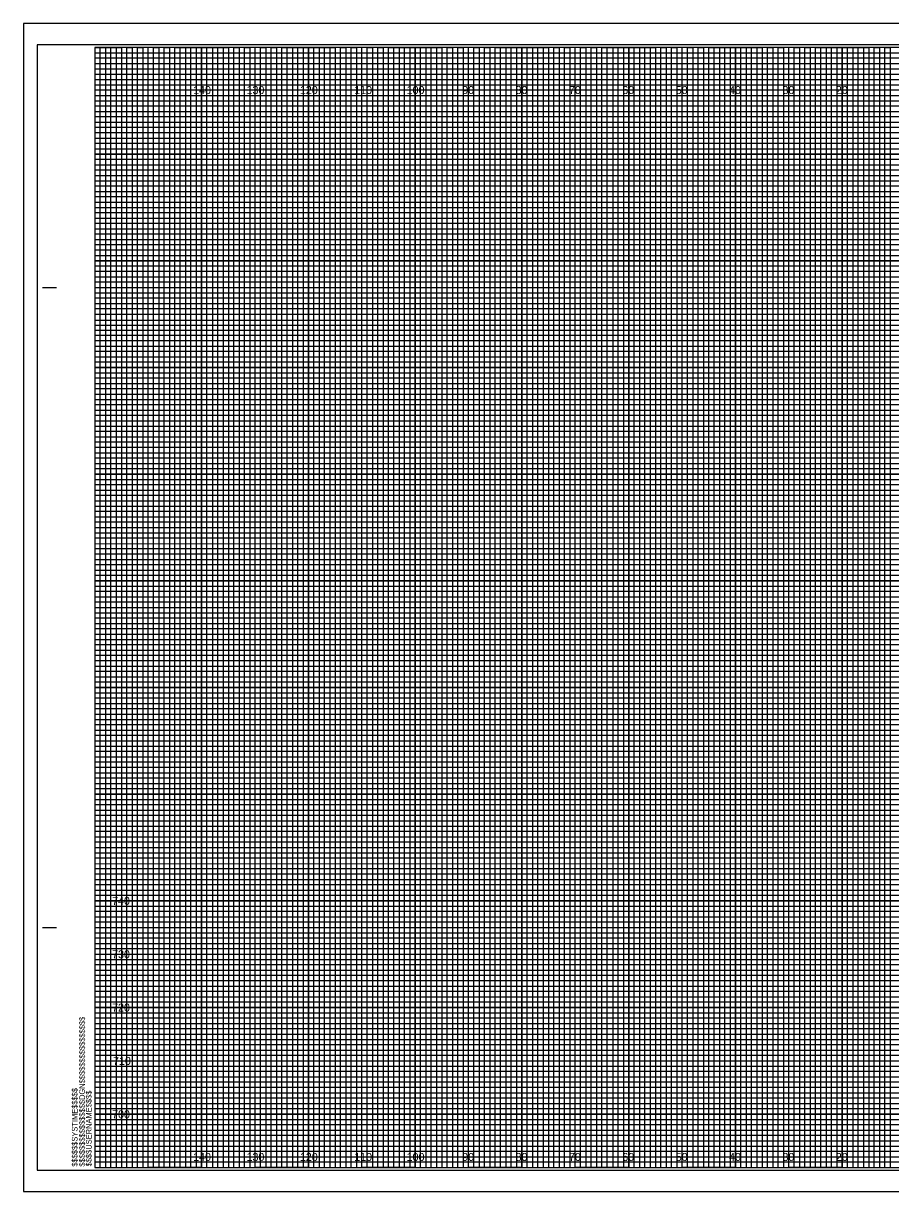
# Model space of a CAD drawing. Extents: x -13 to 323, y -5 to 534.
# Drawn here: x -13.4 to 149.1, y 315.5 to 534.5 of the extents above; entities that cross this region are included whole.
import ezdxf

# ---------------------------------------------------------------- set-up
doc = ezdxf.new("R2010")
doc.units = 0
for name, color, linetype in [('Prop XS Elevation Labels', 7, 'Continuous'), ('Prop XS Offset Labels', 7, 'Continuous'), ('Sheet Cross Section CELL', 7, 'Continuous'), ('Sheet Cross Section Grid Major CELL', 7, 'Continuous'), ('Sheet Cross Section Grid Middle CELL', 7, 'Continuous'), ('Sheet Cross Section Grid Minor 1 CELL', 7, 'Continuous'), ('Sheet Cross Section Grid Minor 2 CELL', 7, 'Continuous'), ('Sheet Cutting Line CELL', 7, 'Continuous'), ('Sheet DOT Grid CELL', 7, 'Continuous'), ('Sheet Plot Border Inside CELL', 7, 'Continuous'), ('Sheet Plot Border Outside CELL', 7, 'Continuous')]:
    doc.layers.add(name, color=color, linetype=linetype)

msp = doc.modelspace()

# ---------------------------------------------------------------- linework, layer by layer
at = {"layer": 'Sheet Cross Section CELL'}
for p, q in [((-9.8, 485), (-7.3, 485)), ((-9.7, 485), (-7.2, 485)), ((-9.8, 365), (-7.3, 365)), ((-9.7, 365), (-7.2, 365))]:
    msp.add_line(p, q, dxfattribs=at)
msp.add_lwpolyline([(320, 530), (0, 530), (0, 320), (320, 320)], close=True, dxfattribs=at)
at = {"layer": 'Sheet Cross Section Grid Major CELL'}
for p, q in [((10, 530), (0, 530)), ((10, 320), (10, 530)), ((30, 530), (20, 530)), ((20, 530), (20, 320)), ((30, 320), (30, 530)), ((50, 530), (40, 530)), ((40, 530), (40, 320)), ((50, 320), (50, 530)), ((70, 530), (60, 530)), ((60, 530), (60, 320)), ((70, 320), (70, 530)), ((90, 530), (80, 530)), ((80, 530), (80, 320)), ((90, 320), (90, 530)), ((110, 530), (100, 530)), ((100, 530), (100, 320)), ((110, 320), (110, 530)), ((130, 530), (120, 530)), ((120, 530), (120, 320)), ((130, 320), (130, 530)), ((150, 530), (140, 530)), ((140, 530), (140, 320)), ((20, 320), (10, 320)), ((40, 320), (30, 320)), ((60, 320), (50, 320)), ((80, 320), (70, 320)), ((100, 320), (90, 320)), ((120, 320), (110, 320)), ((140, 320), (130, 320))]:
    msp.add_line(p, q, dxfattribs=at)
for points in [[(0, 520), (320, 520), (320, 510), (0, 510)], [(0, 500), (320, 500), (320, 490), (0, 490)], [(0, 480), (320, 480), (320, 470), (0, 470)], [(0, 460), (320, 460), (320, 450), (0, 450)], [(0, 440), (320, 440), (320, 430), (0, 430)], [(0, 420), (320, 420), (320, 410), (0, 410)], [(0, 400), (320, 400), (320, 390), (0, 390)], [(0, 380), (320, 380), (320, 370), (0, 370)], [(0, 360), (320, 360), (320, 350), (0, 350)], [(0, 340), (320, 340), (320, 330), (0, 330)]]:
    msp.add_lwpolyline(points, dxfattribs=at)
at = {"layer": 'Sheet Cross Section Grid Middle CELL'}
for points in [[(0, 530), (5, 530), (5, 320), (15, 320), (15, 530), (25, 530), (25, 320), (35, 320), (35, 530), (45, 530), (45, 320), (55, 320), (55, 530), (65, 530), (65, 320), (75, 320), (75, 530), (85, 530), (85, 320), (95, 320), (95, 530), (105, 530), (105, 320), (115, 320), (115, 530), (125, 530), (125, 320), (135, 320), (135, 530), (145, 530), (145, 320), (155, 320)], [(0, 525), (275, 525)], [(0, 505), (320, 505), (320, 515), (0, 515)], [(0, 485), (320, 485), (320, 495), (0, 495)], [(0, 465), (320, 465), (320, 475), (0, 475)], [(0, 445), (320, 445), (320, 455), (0, 455)], [(0, 425), (320, 425), (320, 435), (0, 435)], [(0, 405), (320, 405), (320, 415), (0, 415)], [(0, 385), (320, 385), (320, 395), (0, 395)], [(0, 365), (320, 365), (320, 375), (0, 375)], [(0, 345), (320, 345), (320, 355), (0, 355)], [(0, 325), (320, 325), (320, 335), (0, 335)]]:
    msp.add_lwpolyline(points, dxfattribs=at)
at = {"layer": 'Sheet Cross Section Grid Minor 1 CELL'}
for p, q in [((0, 529), (260, 529)), ((260, 527.98), (0, 527.98)), ((0, 527.98), (0, 527)), ((0, 527), (260, 527)), ((260, 525.89), (0, 525.89)), ((0, 525.89), (0, 524)), ((0, 524), (320, 524))]:
    msp.add_line(p, q, dxfattribs=at)
for points in [[(0, 523), (270, 523), (320, 523), (320, 522), (0, 522)], [(0, 521), (320, 521), (320, 519), (0, 519)], [(0, 518), (320, 518), (320, 517), (0, 516.98)], [(0, 516), (320, 516), (320, 514), (0, 514)], [(0, 513), (320, 513), (320, 512), (0, 512)], [(0, 511), (320, 511), (320, 509), (0, 509)], [(0, 508), (320, 508), (320, 507), (0, 507)], [(0, 506), (320, 506), (320, 504), (0, 504)], [(0, 503), (320, 503), (320, 502), (0, 502)], [(0, 501), (320, 501), (320, 499), (0, 499)], [(0, 498), (320, 498), (320, 497), (0, 497)], [(0, 496), (320, 496), (320, 493.95), (320, 493), (320, 492), (0, 492)], [(0, 494), (320, 494), (320, 493), (0, 493)], [(0, 491), (320, 491), (320, 489), (0, 489.03)], [(0, 489.03), (320, 489), (320, 488), (0, 488)], [(0, 487), (320, 487), (320, 486), (0, 486)], [(0, 484), (320, 484), (320, 483), (0, 483)], [(0, 482), (320, 482), (320, 481), (0, 481)], [(-0.07, 478.89), (320, 478.89), (320, 477.88), (-0.07, 477.88)], [(0, 477), (320, 477), (320, 476), (0, 476)], [(0, 474), (320, 474), (320, 473), (0, 473)], [(0, 472), (320, 472), (320, 471), (0, 471)], [(0, 469), (320, 469), (320, 468), (0, 468)], [(0, 467), (320, 467), (320, 466), (0, 466)], [(0, 464), (320, 464), (320, 463), (0, 463)], [(0, 462), (320, 462), (320, 461), (0, 461)], [(0, 459), (320, 459), (319.99, 457.98), (0, 458)], [(0, 457), (320, 457), (320, 456), (0, 456)], [(0, 454), (320, 454), (320, 453), (0, 453)], [(0, 452), (320, 452), (320, 451), (0, 451)], [(0, 449), (320, 449), (320, 448), (0, 448)], [(0, 447), (320, 447), (320, 446), (0, 446)], [(0, 444), (320, 444), (320, 443), (0, 443)], [(0, 442), (320, 442), (320, 441), (0, 441)], [(0, 439), (320, 439), (320, 438), (0, 438)], [(0, 436.99), (320.07, 436.91), (320, 436), (0, 436)], [(0, 434), (320, 434), (320, 433), (0, 433)], [(0, 432), (320, 432), (320, 431), (0, 431)], [(0, 429), (320, 429), (320, 428), (0, 428)], [(0, 427), (320, 427), (320, 426), (0, 426)], [(0, 424), (320, 424), (320, 423), (0, 423)], [(0, 422), (320, 422), (320, 421), (0, 421)], [(0, 419), (320, 419), (320, 418), (0, 418)], [(0, 417), (320, 417), (320, 416), (0, 416)], [(0, 414), (320, 414), (320, 413), (0, 413)], [(0, 412), (320, 412), (320, 411), (0, 411)], [(0, 409), (320, 409), (320, 408), (0, 408)], [(0, 407), (320, 407), (320, 406), (0, 406)], [(0, 404), (320, 404), (320, 403), (0, 403)], [(0, 402), (320, 402), (320, 401), (0, 401)], [(0, 399), (320, 399), (319.99, 397.98), (0, 398)], [(0, 397), (320, 397), (320, 396), (0, 396)], [(0, 394), (320, 394), (320, 393), (0, 393)], [(0, 392), (320, 392), (320, 391), (0, 391)], [(0, 389), (320, 389), (320, 388), (0, 388)], [(0, 387), (320, 387), (320, 386), (0, 386)], [(0, 384), (320, 384), (320, 383), (0, 383)], [(0, 382), (320, 382), (320, 381), (0, 381)], [(0, 379), (320, 379), (320, 378), (0, 378)], [(0, 376.99), (320.07, 376.91), (320, 376), (0, 376)], [(0, 374), (320, 374), (320, 373), (0, 373)], [(0, 372), (320, 372), (320, 371), (0, 371)], [(0, 369), (320, 369), (320, 368), (0, 368)], [(0, 367), (320, 367), (320, 366), (0, 366)], [(0, 364), (320, 364), (320, 363), (0, 363)], [(0, 362), (320, 362), (320, 361), (0, 361)], [(0, 359), (320, 359), (320, 358), (0, 358)], [(0, 357), (320, 357), (320, 356), (0, 356)], [(0, 354), (320, 354), (320, 353), (0, 353)], [(0, 352), (320, 352), (320, 351), (0, 351)], [(0, 349), (320, 349), (320, 348), (0, 348)], [(0, 347), (320, 347), (320, 346), (0, 346)], [(0, 344), (320, 344), (320, 343), (0, 343)], [(0, 342), (320, 342), (320, 341), (0, 341)], [(0, 339), (320, 339), (320, 338), (0, 338)], [(0, 337), (320, 337), (320, 336), (0, 336)], [(0, 334), (320, 334), (320, 333), (0, 333)], [(0, 332), (320, 332), (320, 331), (0, 331)], [(0, 329), (320, 329), (320, 328), (0, 328)], [(0, 327), (320, 327), (320, 326), (0, 326)], [(0, 324), (320, 324), (320, 323), (0, 323)], [(0, 322), (320, 322), (320, 321), (0, 321)]]:
    msp.add_lwpolyline(points, dxfattribs=at)
at = {"layer": 'Sheet Cross Section Grid Minor 2 CELL'}
for points in [[(0, 320), (1, 320), (1, 530), (2, 530), (2, 320)], [(2, 320), (3, 320), (3, 530), (4, 530), (4, 320)], [(5, 320), (6, 320), (6, 530), (7, 530), (7, 320)], [(7, 320), (8, 320), (8, 530), (9, 530), (9, 320)], [(10, 320), (11, 320), (11, 530), (12, 530), (12, 320)], [(12, 320), (13, 320), (13, 530), (14, 530), (14, 320)], [(15, 320), (16, 320), (16, 530), (17, 530), (17, 320)], [(17, 320), (18, 320), (18, 530), (19, 530), (19, 320)], [(20, 320), (21, 320), (21, 530), (22, 530), (22, 320)], [(22, 320), (23, 320), (23, 530), (24, 530), (24, 320)], [(25, 320), (26, 320), (26, 530), (27, 530), (27, 320)], [(27, 320), (28, 320), (28, 530), (29, 530), (29, 320)], [(30, 320), (31, 320), (31, 530), (32, 530), (32, 320)], [(32, 320), (33, 320), (33, 530), (34, 530), (34, 320)], [(35, 320), (36, 320), (36, 530), (37, 530), (37, 320)], [(37, 320), (38, 320), (38, 530), (39, 530), (39, 320)], [(40, 320), (41, 320), (41, 530), (42, 530), (42, 320)], [(42, 320), (43, 320), (43, 530), (44, 530), (44, 320)], [(45, 320), (46, 320), (46, 530), (47, 530), (47, 320)], [(47, 320), (48, 320), (48, 530), (49, 530), (49, 320)], [(50, 320), (51, 320), (51, 530), (52, 530), (52, 320)], [(52, 320), (53, 320), (53, 530), (54, 530), (54, 320)], [(55, 320), (56, 320), (56, 530), (57, 530), (57, 320)], [(57, 320), (58, 320), (58, 530), (59, 530), (59, 320)], [(60, 320), (61, 320), (61, 530), (62, 530), (62, 320)], [(62, 320), (63, 320), (63, 530), (64, 530), (64, 320)], [(65, 320), (66, 320), (66, 530), (67, 530), (67, 320)], [(67, 320), (68, 320), (68, 530), (69, 530), (69, 320)], [(70, 320), (71, 320), (71, 530), (72, 530), (72, 320)], [(72, 320), (73, 320), (73, 530), (74, 530), (74, 320)], [(75, 320), (76, 320), (76, 530), (77, 530), (77, 320)], [(77, 320), (78, 320), (78, 530), (79, 530), (79, 320)], [(80, 320), (81, 320), (81, 530), (82, 530), (82, 320)], [(82, 320), (83, 320), (83, 530), (84, 530), (84, 320)], [(85, 320), (86, 320), (86, 530), (87, 530), (87, 320)], [(87, 320), (88, 320), (88, 530), (89, 530), (89, 320)], [(90, 320), (91, 320), (91, 530), (92, 530), (92, 320)], [(92, 320), (93, 320), (93, 530), (94, 530), (94, 320)], [(95, 320), (96, 320), (96, 530), (97, 530), (97, 320)], [(97, 320), (98, 320), (98, 530), (99, 530), (99, 320)], [(100, 320), (101, 320), (101, 530), (102, 530), (102, 320)], [(102, 320), (103, 320), (103, 530), (104, 530), (104, 320)], [(105, 320), (106, 320), (106, 530), (107, 530), (107, 320)], [(107, 320), (108, 320), (108, 530), (109, 530), (109, 320)], [(110, 320), (111, 320), (111, 530), (112, 530), (112, 320)], [(112, 320), (113, 320), (113, 530), (114, 530), (114, 320)], [(115, 320), (116, 320), (116, 530), (117, 530), (117, 320)], [(117, 320), (118, 320), (118, 530), (119, 530), (119, 320)], [(120, 320), (121, 320), (121, 530), (122, 530), (122, 320)], [(122, 320), (123, 320), (123, 530), (124, 530), (124, 320)], [(125, 320), (126, 320), (126, 530), (127, 530), (127, 320)], [(127, 320), (128, 320), (128, 530), (129, 530), (129, 320)], [(130, 320), (131, 320), (131, 530), (132, 530), (132, 320)], [(132, 320), (133, 320), (133, 530), (134, 530), (134, 320)], [(135, 320), (136, 320), (136, 530), (137, 530), (137, 320)], [(137, 320), (138, 320), (138, 530), (139, 530), (139, 320)], [(140, 320), (141, 320), (141, 530), (142, 530), (142, 320)], [(142, 320), (143, 320), (143, 530), (144, 530), (144, 320)], [(145, 320), (146, 320), (146, 530), (147, 530), (147, 320)], [(147, 320), (148, 320), (148, 530), (149, 530), (149, 320)]]:
    msp.add_lwpolyline(points, dxfattribs=at)
at = {"layer": 'Sheet Cutting Line CELL'}
for p, q in [((323.3, 534.5), (-13.4, 534.5)), ((-13.4, 534.5), (-13.4, 315.5)), ((-13.4, 315.5), (323.3, 315.5))]:
    msp.add_line(p, q, dxfattribs=at)
at = {"layer": 'Sheet DOT Grid CELL'}
for p, q in [((10, 320), (10, 530)), ((20, 320), (20, 530)), ((30, 320), (30, 530)), ((40, 320), (40, 530)), ((50, 320), (50, 530)), ((60, 320), (60, 530)), ((70, 320), (70, 530)), ((80, 320), (80, 530)), ((90, 320), (90, 530)), ((100, 320), (100, 530)), ((110, 320), (110, 530)), ((120, 320), (120, 530)), ((130, 320), (130, 530)), ((140, 320), (140, 530)), ((0, 520), (320, 520)), ((0, 510), (320, 510)), ((0, 500), (320, 500)), ((0, 490), (320, 490)), ((0, 480), (320, 480)), ((0, 470), (320, 470)), ((0, 460), (320, 460)), ((0, 450), (320, 450)), ((0, 440), (320, 440)), ((0, 430), (320, 430)), ((0, 420), (320, 420)), ((0, 410), (320, 410)), ((0, 400), (320, 400)), ((0, 390), (320, 390)), ((0, 380), (320, 380)), ((0, 370), (320, 370)), ((0, 360), (320, 360)), ((0, 350), (320, 350)), ((0, 340), (320, 340)), ((0, 330), (320, 330))]:
    msp.add_line(p, q, dxfattribs=at)
at = {"layer": 'Sheet Plot Border Inside CELL'}
msp.add_lwpolyline([(-10.8, 319.5), (322.4, 319.5), (322.4, 530.5), (-10.8, 530.5)], close=True, dxfattribs=at)
at = {"layer": 'Sheet Plot Border Outside CELL'}
msp.add_lwpolyline([(-13.4, 315.5), (323.3, 315.5), (323.3, 534.5), (-13.4, 534.5)], close=True, dxfattribs=at)

# ---------------------------------------------------------------- texts
at = {"layer": 'Prop XS Elevation Labels'}
for s, p in [('740', (3.22, 369.25)), ('730', (3.22, 359.25)), ('720', (3.22, 349.25)), ('710', (3.4, 339.25)), ('700', (3.22, 329.25))]:
    msp.add_text(s, height=1.5, dxfattribs=at).set_placement(p)
at = {"layer": 'Prop XS Offset Labels'}
for s, p in [('140', (18.4, 521.25)), ('130', (28.4, 521.25)), ('120', (38.4, 521.25)), ('110', (48.58, 521.25)), ('100', (58.4, 521.25)), ('90', (68.81, 521.25)), ('80', (78.81, 521.25)), ('70', (88.81, 521.25)), ('60', (98.81, 521.25)), ('50', (108.81, 521.25)), ('40', (118.81, 521.25)), ('30', (128.81, 521.25)), ('20', (138.81, 521.25)), ('140', (18.4, 321.25)), ('130', (28.4, 321.25)), ('120', (38.4, 321.25)), ('110', (48.58, 321.25)), ('100', (58.4, 321.25)), ('90', (68.81, 321.25)), ('80', (78.81, 321.25)), ('70', (88.81, 321.25)), ('60', (98.81, 321.25)), ('50', (108.81, 321.25)), ('40', (118.81, 321.25)), ('30', (128.81, 321.25)), ('20', (138.81, 321.25))]:
    msp.add_text(s, height=1.5, dxfattribs=at).set_placement(p)
at = {"layer": 'Sheet Cross Section CELL'}
for s, p in [('$$$$$$$$$$$$$$$$DGN$$$$$$$$$$$$$$$$', (-1.88, 320.18)), ('$$$$$$SYSTIME$$$$$', (-3.26, 320.18)), ('$$$$USERNAME$$$$', (-0.62, 320.23))]:
    msp.add_text(s, height=1.05, rotation=90, dxfattribs=at).set_placement(p)

doc.saveas('drawing.dxf')
